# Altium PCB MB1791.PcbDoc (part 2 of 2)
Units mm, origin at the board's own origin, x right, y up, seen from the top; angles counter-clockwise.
Board outline 68.69 x 34.35 mm, 2 copper layers (Top Layer, Bottom Layer), stack 0.78 mm thick; 94 components, 70 nets, 269 pads, 1128 vias.
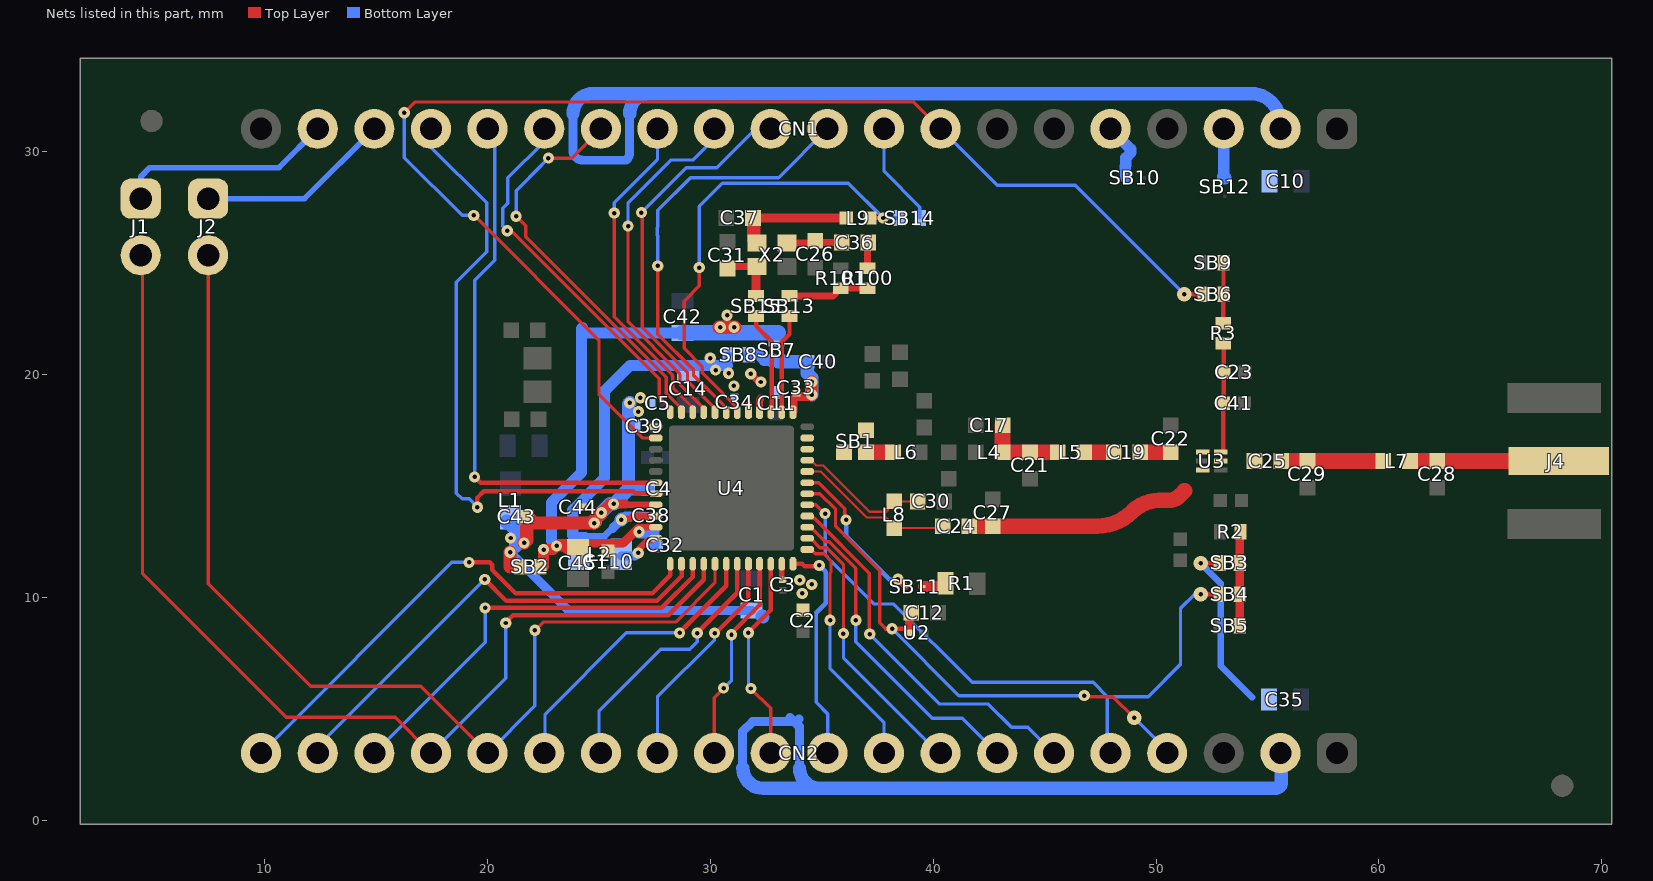
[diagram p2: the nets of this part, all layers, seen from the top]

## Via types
v1: diameter 0.5, hole 0.2, Top Layer to Bottom Layer, 1122 vias
v2: diameter 0.65, hole 0.2, Top Layer to Bottom Layer, 6 vias

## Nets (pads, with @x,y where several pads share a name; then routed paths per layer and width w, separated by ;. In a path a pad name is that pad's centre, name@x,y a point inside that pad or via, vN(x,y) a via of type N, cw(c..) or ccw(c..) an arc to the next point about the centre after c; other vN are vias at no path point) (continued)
NetC17_2: C17.2 C21.2 L4.2 L5.1 | length 3.7
  Top Layer w0.7: C17.2@43.117,17.72 43.112,17.715 L4.2@43.112,16.52 C21.2@44.349,16.52 L5.1@45.585,16.52
NetC19_1: C19.1 C22.2 U3.1 | length 1.4
  Top Layer w0.7: C19.1@49.295,16.52 C22.2@50.655,16.52
NetC19_2: C19.2 L5.2 | length 1.3
  Top Layer w0.7: L5.2@46.783,16.52 C19.2@48.061,16.52
NetC23_2: C23.2 C41.1 R3.1 U3.6 | length 4.9
  Top Layer w0.2: U3.6@52.9,16.52 53.019,16.639 C41.1@53.019,18.704 53.034,18.718 C23.2@53.034,20.104 53.034,21.384 R3.1@53.014,21.404
NetC24_2: C24.2 C27.2 U3.3 | length 10.3
  Top Layer w0.7: C24.2@41.666,13.197 C27.2@42.681,13.197 42.681,13.203 47.371,13.203 ccw(c47.371,15.407) 48.93,13.848 ; 49.09,14.009 48.931,13.849 ; 51.046,14.553 cw(c50.567,15.033) 50.567,14.355 50.153,14.355 ccw(c50.153,12.625) 48.931,13.849 ; 51.047,14.554 51.275,14.782 ; 48.93,13.848 cw(c50.153,12.625) 48.931,13.849 ; 48.93,13.848 48.931,13.849
NetC25_1: C25.1 U3.5
NetC25_2: C25.2 C29.1 L7.1 | length 4.6
  Top Layer w0.7: C25.2@55.613,16.12 C29.1@56.792,16.121 L7.1@60.196,16.12
NetC26_1: C26.1 C36.2 X2.1 | length 2.6
  Top Layer w0.2: X2.1@33.255,25.898 X2.1@33.445,25.898 ; C26.1@34.657,25.898 C26.1@34.679,25.92
  Top Layer w0.3: X2.1@33.445,25.898 C26.1@34.657,25.898 ; C26.1@34.679,25.92 C36.2@35.86,25.92
NetC28_1: C28.1 J4.1 L7.2 | length 6.7
  Top Layer w0.7: L7.2@61.394,16.12 62.568,16.12 J4.1@68.06,16.12
NetC31_1: C31.1 SB15.2 X2.3 | length 2.7
  Top Layer w0.254: C31.1@30.778,24.793 C31.1@30.833,24.848
  Top Layer w0.3: C31.1@30.833,24.848 X2.3@32.095,24.848
  Top Layer w0.4: SB15.2@32.06,23.52 32.06,24.813 X2.3@32.095,24.848
NetC36_1: C36.1 R100.2 | length 1.1
  Top Layer w0.3: R100.2@37.06,24.77 C36.1@37.06,25.918
NetC37_2: C37.2 L9.1 X2.2 | length 5.3
  Top Layer w0.4: C37.2@31.958,27.02 L9.1@36.06,27.02
  Top Layer w0.625: C37.2@31.958,27.02 31.958,26.035 X2.2@32.095,25.898
NetCN1_3: CN1.3 SB12.1 | length 2.2
  Bottom Layer w0.5: SB12.1@53.04,28.863 CN1.3@53.04,31.02
  Bottom Layer w0.6: SB12.1@53.04,28.863 SB12.1@53.077,28.826
NetCN1_5: CN1.5 SB10.1 | length 2.7
  Bottom Layer w0.5: CN1.5@47.96,31.02 48.877,30.103 48.877,29.954 48.643,29.72 48.643,29.37 48.618,29.345 48.618,29.055 48.643,29.03 SB10.1@48.643,28.825
NetL2_2: L2.2 U4.47 | length 2
  Top Layer w0.3: v1(26.78,12) 26.818,12.038 26.818,12.168 27.222,12.572 27.328,12.572 27.408,12.652 U4.47@27.558,12.652
  Bottom Layer w0.4: L2.2@26.032,11.86 26.622,11.86 v1@26.8,12.037
NetL6_1: L6.1 SB1.2 | length 1.2
  Top Layer w0.7: SB1.2@36.991,16.52 L6.1@38.203,16.52
NetR1_2: R1.2 SB11.1 | length 1
  Top Layer w0.5: SB11.1@39.585,10.489 40.429,10.489 R1.2@40.56,10.62
NetR2_2: R2.2 SB3.2 SB4.2 SB5.2 | length 4.2
  Top Layer w0.4: SB5.2@53.754,8.734 SB4.2@53.754,10.148 SB3.2@53.754,11.548 53.754,12.916 R2.2@53.786,12.948
NetR3_2: R3.2 SB6.2 SB9.2 | length 2.7
  Top Layer w0.2: R3.2@53.014,22.304 53.014,23.592 SB6.2@53.027,23.604 SB9.2@53.027,25.005
NetR100_1: R100.1 R101.1 SB13.2 | length 3.8
  Top Layer w0.2: SB13.2@33.56,23.52 SB13.2@33.66,23.62
  Top Layer w0.3: SB13.2@33.56,23.52 35.51,23.52 R101.1@35.86,23.87 R100.1@37.06,23.87
NetSB1_1: SB1.1 U4.23
NetSB1_3: SB1.3 U4.22
NetSB11_2: SB11.2 U4.19 | length 7
  Top Layer w0.15: U4.19@34.356,15.152 34.871,15.152 36.04,13.983 v1@36.04,13.5
  Top Layer w0.2: v1(38.42,10.82) v1@38.429,10.82
  Top Layer w0.3: v1@38.429,10.82 SB11.2@38.76,10.489
  Bottom Layer w0.2: v1(36.1,13.48) 36.1,12.84 36.06,12.8 38.06,10.8 38.42,10.8 v1(38.42,10.82)
NetSB13_1: SB13.1 U4.26 | length 4.5
  Top Layer w0.2: U4.26@33.218,18.302 33.218,21.458 33.56,21.8 SB13.1@33.56,22.62
NetSB15_1: SB15.1 U4.27 | length 4.6
  Top Layer w0.2: SB15.1@32.06,22.62 32.06,22.18 32.77,21.47 32.77,18.354 U4.27@32.718,18.302
NRST: C12.1 CN2.4 U2.1 U4.18 | length 24.6
  Top Layer w0.15: U4.18@34.356,14.652 34.925,14.652 35.625,13.952 35.625,13.195 37.615,11.205 37.615,8.865 37.88,8.6 ; v1(46.779,5.598) 46.757,5.576 46.757,5.554 48.065,5.554 v2(49.02,4.598)
  Top Layer w0.2: 37.88,8.6 v1(38.16,8.6) 38.868,8.6 U2.1@38.948,8.52 ; C12.1@38.948,9.208 C12.1@39.06,9.32
  Top Layer w0.4: U2.1@38.948,8.52 C12.1@38.948,9.208
  Bottom Layer w0.15: v1(38.16,8.6) 41.162,5.598 v1(46.779,5.598) ; v2(49.02,4.598) 50.5,3.119 CN2.4@50.5,3.02
PA0: CN2.14 U4.7 | length 11.8
  Top Layer w0.2: v1(29.42,8.4) 29.42,8.42 31.218,10.218 U4.7@31.218,11.505
  Bottom Layer w0.15: CN2.14@25.1,3.02 25.015,3.105 25.015,4.905 27.793,7.683 29.087,7.683 29.42,8.017 v1(29.42,8.4)
PA1: CN2.13 U4.8 | length 10.2
  Top Layer w0.2: v1(30.2,8.4) 30.24,8.4 31.718,9.878 U4.8@31.718,11.505
  Bottom Layer w0.15: CN2.13@27.64,3.02 27.64,5.542 30.2,8.102 v1(30.2,8.4)
PA2: CN2.12 U4.9 | length 9.3
  Top Layer w0.15: CN2.12@30.18,3.02 30.18,5.51 v1(30.608,5.938)
  Top Layer w0.2: v1@30.96,8.4 32.218,9.658 U4.9@32.218,11.505
  Bottom Layer w0.15: v1(30.608,5.938) 30.96,6.29 v1(30.96,8.33)
PA3: CN2.11 U4.10 | length 9.4
  Top Layer w0.15: v1(31.832,5.917) 32.72,5.028 CN2.11@32.72,3.02
  Top Layer w0.2: v1@31.66,8.38 32.718,9.438 U4.10@32.718,11.505
  Bottom Layer w0.15: v1(31.72,8.42) 31.72,6.028 v1(31.832,5.917)
PA4: CN2.10 U4.12 | length 10.2
  Top Layer w0.2: U4.12@33.718,11.505 34.135,11.505 34.247,11.393 34.852,11.393 v1(34.897,11.438)
  Bottom Layer w0.15: 34.76,9.311 34.76,5.291 35.278,4.773 35.278,3.038 CN2.10@35.26,3.02
  Bottom Layer w0.2: 34.76,9.311 35.186,9.737 35.186,11.149 v1(34.897,11.438) v1@34.86,11.401
PA5: CN2.9 U4.13 | length 10.9
  Top Layer w0.15: U4.13@34.356,12.152 34.537,12.152 34.726,11.963 35.114,11.963 35.422,11.655 35.422,11.13 35.38,11.088 v1(35.38,8.98)
  Bottom Layer w0.15: v1(35.38,8.98) 35.38,6.803 37.8,4.383 CN2.9@37.8,3.02
PA6: CN2.8 U4.14 | length 12.4
  Top Layer w0.15: U4.14@34.356,12.652 34.507,12.652 34.926,12.233 35.226,12.233 35.98,11.479 v1(35.98,8.38)
  Bottom Layer w0.15: v1(35.98,8.38) 35.98,7.305 40.265,3.02 CN2.8@40.34,3.02
PA7: CN2.7 U4.15 | length 14.7
  Top Layer w0.15: U4.15@34.356,13.152 34.507,13.152 35.156,12.503 35.338,12.503 36.54,11.301 v1(36.54,8.98)
  Bottom Layer w0.15: v1(36.54,8.98) 36.54,8.004 39.958,4.585 41.315,4.585 CN2.7@42.88,3.02
PA8: CN2.6 U4.16 | length 17.1
  Top Layer w0.15: U4.16@34.356,13.652 34.574,13.652 34.645,13.58 34.645,13.542 34.684,13.542 37.14,11.085 v1@37.14,8.46
  Top Layer w0.2: v1@37.14,8.46 37.14,8.38 v1(37.16,8.36) 37.16,8.4 v1@37.18,8.42
  Bottom Layer w0.15: v1(37.16,8.36) 40.3,5.219 42.484,5.219 43.518,4.185 44.255,4.185 CN2.6@45.42,3.02
PA9: CN2.5 SB4.1 U4.17 | length 29.1
  Top Layer w0.15: U4.17@34.356,14.152 34.748,14.152 35.14,13.76 v1@35.14,13.7
  Top Layer w0.2: v2(51.997,10.139) 52.846,10.139 SB4.1@52.854,10.148
  Bottom Layer w0.15: v1(35.16,13.76) 35.16,11.917 35.422,11.655 35.422,11.645 37.361,9.705 38.247,9.705 41.762,6.19 47.185,6.19 47.82,5.554 ; CN2.5@47.96,3.02 47.82,3.16 47.82,5.554 ; v2(51.997,10.139) 51.73,10.139 51.098,9.507 51.098,7.006 49.647,5.554 47.82,5.554
PA10: CN1.12 U4.33 | length 16.3
  Top Layer w0.15: v1(26.32,26.66) 26.32,22.356 28.577,20.099 28.577,20.096 28.648,20.025 28.648,19.562 29.718,18.492 U4.33@29.718,18.302
  Bottom Layer w0.15: v1(26.32,26.66) 26.32,27.699 28.241,29.621 29.227,29.621 30.18,30.573 CN1.12@30.18,31.02
PA11: CN1.13 U4.34 | length 15
  Top Layer w0.15: v1(25.7,27.24) 25.7,22.594 28.307,19.987 28.307,19.935 28.326,19.916 28.326,19.404 U4.34@29.218,18.512
  Top Layer w0.2: U4.34@29.218,18.302 U4.34@29.218,18.512
  Bottom Layer w0.15: v1(25.7,27.24) 25.7,27.701 27.64,29.641 CN1.13@27.64,31.02
PA12: CN1.14 U4.35 | length 18.1
  Top Layer w0.15: v1@21.27,27.15 v1@21.35,27.15 ; v1(21.3,27.1) 21.73,26.67 21.73,26.182 28.037,19.875 28.037,19.152 28.718,18.471 U4.35@28.718,18.302 ; v1(22.75,29.703) 23.783,29.703 CN1.14@25.1,31.02
  Bottom Layer w0.15: v1(21.3,27.1) 21.3,28.249 22.47,29.42 22.47,29.424 v1(22.75,29.703)
PA13: CN1.15 U4.36 | length 16.7
  Top Layer w0.15: v1(20.899,26.446) 20.981,26.365 21.164,26.365 27.725,19.803 27.725,18.976 28.218,18.482 U4.36@28.218,18.302
  Bottom Layer w0.15: v1(20.899,26.446) 20.705,26.641 20.705,27.452 20.931,27.679 20.931,28.82 22.56,30.449 CN1.15@22.56,31.02
PA14: CN1.16 U4.42 | length 24.5
  Top Layer w0.2: v1(19.437,15.408) 19.705,15.14 27.618,15.14 U4.42@27.66,15.182
  Bottom Layer w0.15: v1(19.437,15.408) 19.437,24.224 20.341,25.128 20.341,30.699 CN1.16@20.02,31.02 CN1.16@20.008,31.008
PA15: CN1.17 U4.43 | length 27.8
  Top Layer w0.2: v1(19.564,14.048) 19.564,14.482 19.852,14.77 26.543,14.77 26.646,14.666 27.629,14.666 U4.43@27.653,14.69
  Bottom Layer w0.15: CN1.17@17.48,31.02 17.48,30.202 19.981,27.7 19.981,25.508 18.62,24.147 18.62,14.678 18.877,14.421 19.191,14.421 v1(19.564,14.048)
PB0: L9.2 SB14.1 U4.30 | length 21.2
  Top Layer w0.15: v1(29.514,24.793) 29.514,23.975 28.833,23.294 28.833,21.177 29.651,20.359 29.651,20.076 U4.30@31.218,18.508 ; U4.30@31.155,18.365 U4.30@31.218,18.302 U4.30@31.218,18.508 ; U4.30@31.218,18.514 U4.30@31.218,18.508
  Top Layer w0.2: L9.2@37.22,27.02 v1(37.76,27.02)
  Bottom Layer w0.15: v1(29.514,24.793) 29.514,27.539 30.554,28.578 36.202,28.578 v1(37.76,27.02)
  Bottom Layer w0.2: v1(37.76,27.02) SB14.1@38.51,27.02
PB2: CN1.10 U4.31 | length 19.5
  Top Layer w0.15: v1(27.654,24.873) 27.654,21.812 29.255,20.212 29.255,19.967 30.718,18.504 U4.31@30.718,18.302
  Bottom Layer w0.15: v1(27.654,24.873) 27.654,26.225 27.635,26.244 27.635,26.596 27.654,26.615 27.654,27.362 29.121,28.828 33.068,28.828 CN1.10@35.26,31.02
PB3: CN2.20 U4.1 | length 23.4
  Top Layer w0.2: v1@19.197,11.581 20.111,11.581 20.234,11.458 20.234,11.234 21.288,10.18 27.4,10.18 28.211,10.991 U4.1@28.211,11.505
  Bottom Layer w0.15: CN2.20@9.86,3.02 18.415,11.575 v1(19.191,11.575)
PB4: CN2.19 U4.2 | length 20.8
  Top Layer w0.2: v1(19.892,10.814) 20.848,9.857 27.617,9.857 28.718,10.958 U4.2@28.718,11.505
  Bottom Layer w0.15: CN2.19@12.4,3.322 v1(19.892,10.814)
PB5: CN2.18 U4.3 | length 19
  Top Layer w0.2: v1(19.908,9.535) 20.558,9.533 27.833,9.533 29.218,10.918 U4.3@29.218,11.505
  Bottom Layer w0.15: CN2.18@14.94,3.02 19.908,7.988 v1(19.908,9.535)
PB6: CN2.17 J1.2 U4.4 | length 48.2
  Top Layer w0.15: J1.2@4.46,25.35 4.538,25.272 4.538,11.077 10.992,4.623 15.877,4.623 CN2.17@17.48,3.02
  Top Layer w0.2: v1(20.836,8.855) 20.84,8.889 21.16,9.209 28.129,9.209 29.718,10.798 U4.4@29.718,11.505
  Bottom Layer w0.15: CN2.17@17.48,3.02 20.836,6.376 v1(20.836,8.855)
PB7: CN2.16 J2.2 U4.5 | length 46.6
  Top Layer w0.15: J2.2@7.485,25.348 7.485,10.61 12.08,6.015 17.025,6.015 CN2.16@20.02,3.02 ; v1@22.141,8.532 22.506,8.896 28.456,8.896 30.218,10.658 U4.5@30.218,11.505
  Bottom Layer w0.15: CN2.16@20.02,3.02 22.139,5.139 v1(22.139,8.53)
PB8: CN2.15 U4.6 | length 14.2
  Top Layer w0.15: U4.6@30.678,11.465 U4.6@30.718,11.505 U4.6@30.718,11.255
  Top Layer w0.2: v1@28.62,8.36 v1@28.66,8.4 ; v1@28.7,8.4 v1@28.66,8.4 ; U4.6@30.72,11.255 U4.6@30.72,11.58 ; U4.6@30.72,11.465 U4.6@30.72,11.58 ; v1@28.66,8.4 28.64,8.4 v1(28.63,8.41) 28.62,8.42 30.72,10.52 U4.6@30.72,11.58
  Bottom Layer w0.15: CN2.15@22.56,3.02 22.596,3.056 22.596,4.761 26.244,8.41 v1(28.63,8.41)
PB12: CN1.11 U4.32 | length 17.8
  Top Layer w0.15: v1@26.96,27.2 26.96,22.125 28.985,20.1 28.985,19.716 30.218,18.483 U4.32@30.218,18.302
  Bottom Layer w0.15: v1(26.92,27.26) 28.933,29.273 30.298,29.273 32.045,31.02 CN1.11@32.72,31.02 CN1.11@32.72,30.844
PC13: CN1.8 SB6.1 U4.38 | length 59.7
  Top Layer w0.15: v1(16.28,31.74) 16.76,32.22 39.14,32.22 CN1.8@40.34,31.02 ; v1@19.266,27.14 v1(19.4,27.14) ; v1@19.35,27.21 25.015,21.545 25.015,19.108 26.971,17.152 U4.38@27.558,17.152
  Top Layer w0.2: v2(51.274,23.6) SB6.1@52.122,23.6
  Bottom Layer w0.15: v1(16.28,31.74) 16.287,31.733 16.287,29.728 18.875,27.14 v1(19.4,27.14) ; CN1.8@40.34,31.02 42.869,28.491 46.383,28.491 v2(51.274,23.6)
RFI_N: C30.2 L8.2 U4.21 | length 6.1
  Top Layer w0.1: U4.21@34.578,16.095 34.759,15.914 35.077,15.914 37.147,13.845 37.905,13.845 37.964,13.904 37.964,14.012 L8.2@38.264,14.312 ; L8.2@38.398,14.446 L8.2@38.264,14.312 ; C30.2@39.276,14.307 38.269,14.307 L8.2@38.264,14.312
RFI_P: C24.1 L8.1 U4.20 | length 7.3
  Top Layer w0.1: U4.20@34.356,15.652 34.357,15.651 34.968,15.651 37.037,13.581 37.905,13.581 37.964,13.523 37.964,13.414 L8.1@38.264,13.114 40.385,13.114 C24.1@40.468,13.197
UART_RX: CN1.18 J2.1 | length 8.8
  Bottom Layer w0.254: J2.1@7.485,27.888 11.808,27.888 CN1.18@14.94,31.02
UART_TX: CN1.19 J1.1 | length 9.8
  Bottom Layer w0.254: J1.1@4.46,27.89 4.46,28.873 4.869,29.281 10.661,29.281 CN1.19@12.4,31.02
VDD: C1.2 C2.2 C3.2 C4.2 C5.2 C35.2 C39.1 C43.2 C44.2 CN2.2 L1.1 SB2.2 SB3.1 U4.11 U4.37 U4.44 | length 71
  Top Layer w0.2: v2(51.997,11.539) 52.846,11.539 SB3.1@52.854,11.548
  Top Layer w0.254: C3.2@33.22,10.9 U4.11@33.22,11.463
  Top Layer w0.3: v1@25.63,14.108 v1@25.674,14.152 ; 26.074,14.212 26.205,14.212 26.265,14.152 U4.44@27.558,14.152
  Top Layer w0.4: v1(25.67,14.195) 26.188,14.195
  Top Layer w0.5: v1(25.127,13.8) 25.522,14.195 v1(25.67,14.195)
  Top Layer w0.6: v1(21.026,12.027) 21.026,11.381 SB2.2@21.376,11.381 ; v1(21.657,12.45) 21.771,12.563 21.771,13.201 ; C43.2@21.803,13.631 22.095,13.338 v1(24.805,13.338) 24.805,13.478 v1(25.127,13.8)
  Bottom Layer w0.3: v2(51.997,11.539) 52.904,10.633 52.904,6.927 54.307,5.524
  Bottom Layer w0.4: v1(21.026,12.027) 23.634,9.418 C1.2@31.859,9.418 ; 31.461,2.547 31.461,3.861 31.461,3.993 31.904,4.435 33.77,4.435 ; 33.579,4.626 33.77,4.435 ; 33.99,4.54 33.885,4.435 33.77,4.435 ; 34.001,2.547 34.001,3.861 34.001,4.204 33.77,4.435
  Bottom Layer w0.45: C4.2@27.212,14.863 C4.2@27.224,14.876
  Bottom Layer w0.6: L1.1@20.871,13.357 20.871,13.433 21.28,13.023 21.28,12.299 ; v1(24.805,13.338) 24.805,13.347 24.849,13.391 24.849,13.522 v1(25.127,13.8) 25.127,13.819 v1@25.523,14.215 ; v1(25.67,14.195) 26.338,14.863 ; v1(26.39,18.729) 26.338,18.677 26.338,14.863 ; C4.2@27.212,14.863 26.338,14.863 ; 31.471,2.346 ccw(c32.377,2.346) 32.377,1.441 55.348,1.441 ccw(c55.348,1.718) 55.625,1.718 55.625,2.975 ccw(c55.58,2.975) CN2.2@55.58,3.02 ; C1.2@32.345,9.15 32.37,9.125 ; 34.011,2.346 ccw(c34.917,2.346) 34.917,1.441
  other v1: 34.134,10.184 34.558,10.583 34.023,10.779 21.052,12.667 26.784,18.335 26.876,18.957
VDD_TCXO_EXT: CN1.9 SB14.2 | length 4.7
  Bottom Layer w0.15: CN1.9@37.8,31.02 37.8,29.115 39.41,27.505 SB14.2@39.41,27.02
VDDPA: C33.2 C40.1 SB7.1 SB8.2 U4.25 | length 6.5
  Top Layer w0.35: U4.25@33.743,18.327 33.743,18.905 C33.2@33.876,19.039
  Top Layer w0.4: C33.2@33.876,19.039 33.903,19.012 v1@34.539,19.012
  Top Layer w0.5: v1@34.558,19.063 v1@34.558,19.713
  Bottom Layer w0.5: SB8.2@31.729,20.818 SB8.2@31.729,20.893 32.163,20.893 32.413,20.643 SB7.1@32.98,20.643 SB7.1@33.047,20.576
  Bottom Layer w0.6: SB7.1@33.047,20.576 C40.1@34.372,20.576 34.362,20.565 34.362,20.05 34.558,19.854 v1(34.558,19.669) v1(34.558,19.093)
VDDRF: C10.1 C11.1 C32.2 C42.1 C45.1 C110.1 CN1.2 SB2.1 SB7.2 U4.28 U4.46 | length 77.9
  Top Layer w0.3: v1@26.696,13.002 v1@26.75,13.002 ; v1@26.758,13.152 U4.46@27.558,13.152 U4.46@27.569,13.152 ; v1(31.825,20.034) 32.194,19.665 v1(32.28,19.665) ; U4.28@32.218,18.302 32.218,18.861 32.262,18.905 32.262,18.959
  Top Layer w0.4: v1(23.114,12.316) 23.23,12.432 26.1,12.432 ; 23.481,12.432 26.1,12.432 ; C45.1@23.594,12.432 26.1,12.432 ; C45.1@24.071,12.432 26.1,12.432 ; v1@26.696,13.002 v1@26.669,13.002 ; v1@26.736,13.069 v1@26.669,13.002 ; 26.1,12.432 v1@26.669,13.002
  Top Layer w0.5: SB2.1@22.386,11.381 22.534,11.381 v1(22.534,12.144) 22.942,12.144 v1(23.114,12.316) 23.481,12.316 C45.1@23.594,12.203
  Top Layer w0.6: v1@30.409,22.128 v1@31.109,22.128
  Bottom Layer w0.4: 23.841,31.493 23.841,30.179 23.841,30.039 ccw(c24.247,30.039) 23.96,29.752 ccw(c24.306,30.098) 24.306,29.609 26.164,29.609 ccw(c26.164,29.758) 26.269,29.653 ccw(c26,29.922) 26.381,29.922 26.381,30.179 26.381,31.493
  Bottom Layer w0.5: v1(22.534,12.144) 22.942,12.144 v1(23.114,12.316) 22.889,12.541 22.889,14.261 24.23,15.603 24.23,22.061 ; 24.283,22.114 24.23,22.061 ; 27.475,12.372 27.475,12.922 ; C42.1@28.764,21.868 24.423,21.868 24.23,22.061
  Bottom Layer w0.6: 23.851,31.694 cw(c24.757,31.694) 24.757,32.599 27.297,32.599 ; 26.391,31.694 cw(c27.297,31.694) 27.297,32.599 ; v1@26.809,12.941 v1@26.828,12.96 ; v1(26.818,12.95) 27.344,12.95 ; CN1.2@55.58,31.02 55.58,31.242 ccw(c54.192,31.242) 55.173,32.224 ccw(c54.267,31.318) 54.267,32.599 27.297,32.599
  Bottom Layer w0.7: C42.1@28.753,21.879 33.043,21.879
  other v1: 30.452,22.122 31.077,22.122 30.764,22.659
VDDRF1V55: C14.1 C34.2 C38.1 L2.1 SB8.1 U4.29 U4.45 | length 20.4
  Top Layer w0.3: v1(26.019,13.486) 26.058,13.524 26.42,13.524 26.547,13.652 U4.45@27.558,13.652 ; U4.29@31.718,18.302 31.718,18.655
  Bottom Layer w0.3: L2.1@24.107,11.94 23.808,12.239 23.808,12.776 23.841,12.776 24.413,12.776 24.45,12.738 25.262,12.738 25.262,12.752 25.668,13.158 ; v1@25.969,13.486 v1(26.019,13.486) ; v1@26.039,13.505 v1(26.019,13.486) ; v1@26.074,13.486 v1(26.019,13.486) ; 30.788,20.407 30.788,20.867 SB8.1@30.83,20.909
  Bottom Layer w0.4: 25.668,13.158 25.668,13.138 25.632,13.101 25.635,13.101 v1(26.019,13.486) ; v1@26.039,13.505 26.198,13.665 C38.1@26.998,13.665
  Bottom Layer w0.5: 23.841,12.776 23.841,13.927 25.266,15.352 25.266,19.258 26.415,20.407 30.788,20.407
  Bottom Layer w0.6: v1(26.019,13.486) v1@26.039,13.505
  other v1: 31.066,19.492 30.832,20.057 30.247,20.201 30.008,20.737
pads on no net: 1.1 1_1.1 ?.1 _1.1 Designator1.1
copper on no net: | length 1771.3
  Top Layer w0.025: 88.999,130.962 91.531,133.494 94.579,136.542 97.627,139.59 100.675,142.638 103.723,145.686 106.771,148.734 109.819,151.782 ; 88.999,132.486 90.007,133.494 93.055,136.542 96.103,139.59 99.151,142.638 102.199,145.686 105.247,148.734 108.295,151.782 ; 88.999,134.01 91.531,136.542 94.579,139.59 97.627,142.638 100.675,145.686 103.723,148.734 106.771,151.782 ; 88.999,135.534 90.007,136.542 93.055,139.59 96.103,142.638 99.151,145.686 102.199,148.734 105.247,151.782 ; 88.999,137.058 91.531,139.59 94.579,142.638 97.627,145.686 100.675,148.734 103.723,151.782 ; 88.999,138.582 90.007,139.59 93.055,142.638 96.103,145.686 99.151,148.734 102.199,151.782 ; 88.999,140.106 91.531,142.638 94.579,145.686 97.627,148.734 100.675,151.782 ; 88.999,141.63 90.007,142.638 93.055,145.686 96.103,148.734 99.151,151.782 ; 88.999,143.154 91.531,145.686 94.579,148.734 97.627,151.782 ; 88.999,144.678 90.007,145.686 93.055,148.734 96.103,151.782 ; 88.999,146.202 91.531,148.734 94.579,151.782 ; 88.999,147.726 90.007,148.734 93.055,151.782 ; 88.999,149.25 91.531,151.782 ; 88.999,150.774 90.007,151.782 ; 90.007,130.446 93.055,133.494 96.103,136.542 99.151,139.59 102.199,142.638 105.247,145.686 108.295,148.734 111.343,151.782 ; 91.531,130.446 94.579,133.494 97.627,136.542 100.675,139.59 103.723,142.638 106.771,145.686 109.819,148.734 112.867,151.782 ; 93.055,130.446 96.103,133.494 99.151,136.542 102.199,139.59 105.247,142.638 108.295,145.686 111.343,148.734 114.391,151.782 ; 94.579,130.446 97.627,133.494 100.675,136.542 103.723,139.59 106.771,142.638 109.819,145.686 112.867,148.734 115.915,151.782 ; 96.103,130.446 99.151,133.494 102.199,136.542 105.247,139.59 108.295,142.638 111.343,145.686 114.391,148.734 117.439,151.782 ; 97.627,130.446 100.675,133.494 103.723,136.542 106.771,139.59 109.819,142.638 112.867,145.686 115.915,148.734 117.439,150.258 ; 99.151,130.446 102.199,133.494 105.247,136.542 108.295,139.59 111.343,142.638 114.391,145.686 117.439,148.734 ; 100.675,130.446 103.723,133.494 106.771,136.542 109.819,139.59 112.867,142.638 115.915,145.686 117.439,147.21 ; 102.199,130.446 105.247,133.494 108.295,136.542 111.343,139.59 114.391,142.638 117.439,145.686 ; 103.723,130.446 106.771,133.494 109.819,136.542 112.867,139.59 115.915,142.638 117.439,144.162 ; 105.247,130.446 108.295,133.494 111.343,136.542 114.391,139.59 117.439,142.638 ; 106.771,130.446 109.819,133.494 112.867,136.542 115.915,139.59 117.439,141.114 ; 108.295,130.446 111.343,133.494 114.391,136.542 117.439,139.59 ; 109.819,130.446 112.867,133.494 115.915,136.542 117.439,138.066 ; 111.343,130.446 114.391,133.494 117.439,136.542 ; 112.867,130.446 115.915,133.494 117.439,135.018 ; 114.391,130.446 117.439,133.494 ; 115.915,130.446 117.439,131.97
  Top Layer w0.381: 2.154,133.494 12.565,133.494 36.181,133.494 58.019,133.494 74.525,133.494 88.999,133.494 117.439,133.494 ; 2.154,136.542 12.565,136.542 36.181,136.542 58.019,136.542 74.525,136.542 88.999,136.542 117.439,136.542 ; 2.154,139.59 12.565,139.59 36.181,139.59 58.019,139.59 74.525,139.59 88.999,139.59 117.439,139.59 ; 2.154,142.638 12.565,142.638 36.181,142.638 58.019,142.638 74.525,142.638 88.999,142.638 117.439,142.638 ; 2.154,145.686 12.565,145.686 36.181,145.686 58.019,145.686 74.525,145.686 88.999,145.686 117.439,145.686 ; 2.154,148.734 12.565,148.734 36.181,148.734 58.019,148.734 74.525,148.734 88.999,148.734 117.439,148.734 ; 2.154,151.782 117.439,151.782 ; 12.565,154.83 12.565,130.446 ; 36.181,154.83 36.181,130.446 ; 58.019,154.83 58.019,130.446 ; 74.525,154.83 74.525,130.446 ; 88.999,154.83 88.999,130.446 ; 12.565,130.446 36.181,130.446 ; 12.565,130.446 2.154,130.446 2.154,154.83 117.439,154.83 117.439,130.446 88.999,130.446 ; 36.181,130.446 58.019,130.446 ; 58.019,130.446 74.525,130.446 ; 74.525,130.446 88.999,130.446

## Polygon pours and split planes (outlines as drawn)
GND on Top Layer "TOP_LAYER_GND" (solid, remove dead copper, pour order 0): 1.751,34.02 70.439,34.02 70.439,0.02 1.751,0.02
GND on Bottom Layer "GND_L04_P002" (solid, remove dead copper, pour order 2): 1.751,34.04 70.439,34.04 70.439,0 1.751,0

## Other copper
Top Layer:
  region net VDD: 33.085,10.655 33.085,10.943 33.49,10.943 33.651,11.002 cw(c34.123,9.716) 34.123,11.086 34.283,11.086 cw(c34.283,10.726) 34.421,11.058 cw(c34.014,10.077) 34.765,10.828 34.817,10.777 cw(c34.585,10.546) 34.912,10.546 34.912,9.867 cw(c34.21,9.867) 34.706,9.37 34.464,9.127 33.863,9.127 33.86,10.284 ccw(c33.557,10.284) 33.675,10.562 33.457,10.655
  region net VDD: 27.52,17.503 27.368,17.503 cw(c27.368,18.022) 27.001,17.655 26.156,18.499 cw(c26.393,18.737) 26.156,18.974 26.481,19.299 cw(c26.839,18.942) 27.196,19.299 cw(c26.912,19.015) 27.314,19.015 27.314,18.331 ccw(c28.018,18.331) 27.486,17.87 cw(c27.38,17.777) 27.52,17.777
  region net NetC15_1: 34.16,17.652 34.16,18.02 36.079,19.838 cw(c36.751,19.128) 36.751,20.105 36.913,20.105 38.91,20.105 38.91,19.347 36.928,19.347 ccw(c36.928,17.777) 35.857,18.925 34.492,17.652
  region net NetC24_2: 51.821,15.775 cw(c51.115,16.07) 51.529,15.426 51.127,15.168 50.976,14.953 51.494,14.59 ccw(c51.533,14.646) 51.589,14.607 51.71,14.781 51.819,15.287 cw(c52.277,15.188) 51.893,15.457 52.019,15.637
  region net VDDRF: 31.666,19.832 31.616,19.881 cw(c31.772,20.037) 31.552,20.037 31.552,20.107 ccw(c31.115,20.108) 31.424,20.417 30.302,21.538 cw(c30.774,22.011) 30.106,22.011 30.106,22.416 cw(c30.658,22.416) 30.658,22.968 30.92,22.968 cw(c30.92,22.414) 31.473,22.414 31.473,21.83 ccw(c32.325,21.83) 31.723,21.228 32.135,20.816 cw(c31.784,20.465) 32.28,20.465 32.28,19.665
  region net VDDRF: 32.063,18.6 32.063,19.035 ccw(c31.094,19.035) 31.779,19.72 31.612,19.888 cw(c31.732,20.008) 31.562,20.008 31.562,20.089 cw(c31.701,20.089) 31.603,20.186 31.678,20.262 cw(c31.759,20.18) 31.759,20.295 31.894,20.295 cw(c31.894,19.981) 32.116,20.203 32.449,19.87 cw(c32.221,19.641) 32.544,19.646 cw(c32.321,19.671) 32.521,19.57 32.521,18.88 cw(c32.403,18.88) 32.486,18.796 32.377,18.6
  region net VDDRF1V55: 29.777,20.907 ccw(c30.004,20.759) 29.813,20.567 29.896,20.484 29.969,20.194 ccw(c30.305,20.279) 30.067,20.028 31.628,18.548 31.865,18.548 31.865,18.677 ccw(c31.296,18.677) 31.698,19.08 31.562,19.215 cw(c31.792,19.445) 31.467,19.445 31.467,19.477 31.467,19.561 ccw(c30.367,19.562) 31.145,20.34 30.611,20.873 ccw(c30.166,20.429) 30.166,21.058 30.056,21.058 ccw(c30.056,20.725)
  region net VDD: 21.501,11.716 20.936,11.716 cw(c20.936,11.97) 20.682,11.97 20.682,12.787 cw(c21.001,12.787) 21.001,13.106 21.696,13.106 cw(c21.696,12.795) 22.006,12.795 22.006,12.398 cw(c21.58,12.398) 21.881,12.096
  region net VDDRF: 22.349,12.308 22.621,12.58 cw(c22.747,12.454) 22.747,12.632 25.99,12.632 26.704,12.715 25.803,11.907 22.477,11.88 cw(c22.477,11.939) 22.428,11.907 22.349,12.024
  region net VDD: 25.47,13.849 25.575,13.849 ccw(c25.575,14.415) 25.975,14.014 25.67,14.195
  region net VDDRF: 26.931,12.736 ccw(c26.926,12.147) 26.513,12.567 26.374,12.706 26.669,13.002
  region net NetC25_1: 52.791,16.232 53.232,16.232 ccw(c53.232,16.998) 53.522,16.289 53.964,16.47 54.227,16.47 54.227,15.77 53.946,15.77 53.47,15.971 ccw(c53.288,15.54) 53.288,16.008 52.791,16.008
  region net NetC19_1: 52.184,16.632 51.744,16.632 cw(c51.744,17.398) 51.454,16.689 51.012,16.87 50.749,16.87 50.749,16.17 51.03,16.17 51.506,16.371 cw(c51.688,15.94) 51.688,16.408 52.184,16.408
  region net NetSB1_1: 34.356,17.301 34.642,17.301 ccw(c34.642,18.013) 35.16,17.525 35.356,17.733 cw(c35.634,17.471) 35.634,17.853 36.991,17.853 36.991,17.153 35.606,17.153 ccw(c35.606,16.827) 35.433,17.103 cw(c35.081,17.664) 35.081,17.002 34.356,17.002
  region net NetSB1_3: 34.425,16.502 34.774,16.502 cw(c34.774,15.705) 35.353,16.252 ccw(c35.544,16.432) 35.544,16.17 35.86,16.17 35.86,16.871 35.546,16.871 35.104,16.801 34.425,16.801
  pour cut-out: 32.12,18.52 32.12,20.72 29.8,23.04 29.8,25.82 30.96,25.82 30.96,27.52 37.86,27.52 37.86,25.82 37.86,23.02 37.36,22.42 35.22,22.42 33.68,20.88 33.68,18.84 33.36,18.52
  pour cut-out: 37.477,11.969 40.809,11.969 40.809,13.968 40.12,13.968 40.12,15.434 36.729,15.434 36.3,15.934 36.3,15.434 36.3,11.963 37.671,11.963
  region net VDD: 24.219,14.226 24.37,14.376 25.551,14.376 25.822,14.105 24.854,13.136 24.219,13.136
  region net NetC28_1: 65.297,16.432 66.247,16.755 66.278,16.755 66.278,15.485 66.217,15.485 65.297,15.807
  pour cut-out: 27.78,18.06 34.1,18.06 34.04,18 34.04,11.78 28.38,11.78 28.38,12.36 27.78,12.36
  pour cut-out: 39.522,9.783 39.585,9.72 39.96,9.72 39.96,8.92 39.46,8.92
  pour cut-out: 31.16,27.42 31.66,27.42 31.66,26.52 31.56,26.62 31.16,26.62
  pour cut-out: 36.46,27.42 36.86,27.42 36.86,26.62 36.46,26.62
  pour cut-out: 36.26,26.32 36.76,26.32 36.76,25.62 36.66,25.52 36.26,25.52
  pour cut-out: 21.6,20.2 22.9,20.2 22.9,19.7 21.6,19.7
  region net GND: 33.76,25.22 35.46,25.22 35.66,25.02 35.66,24.42 35.16,24.42 34.06,24.42 33.96,24.52 33.76,24.52
  pour cut-out: 25.64,13.08 26.2,13.08 26.22,13.06 26.22,12.74 25.64,12.74 25.62,12.76 25.62,13.06
  pour cut-out: 34.16,19.54 34.72,19.54 34.74,19.52 34.74,19.2 34.16,19.2 34.14,19.22 34.14,19.52
  pour cut-out: 32.98,10.66 33.54,10.66 33.56,10.64 33.56,10.32 32.98,10.32 32.96,10.34 32.96,10.64
  text "Layer" at 3.932,152.544 h1.52
  text "Name" at 14.343,152.544 h1.52
  text "Material" at 37.959,152.544 h1.52
  text "Thickness" at 59.797,152.544 h1.52
  text "Constant" at 76.303,152.544 h1.52
  text "Board Layer Stack" at 90.777,152.544 h1.52
  text "Top Overlay" at 14.343,149.496 h1.52
  text "Top Solder" at 14.343,146.448 h1.52
  text "Solder Resist" at 37.959,146.448 h1.52
  text "0.39mil" at 59.797,146.448 h1.52
  text "3.5" at 76.303,146.448 h1.52
  text "1" at 3.932,143.4 h1.52
  text "Top Layer" at 14.343,143.4 h1.52
  text "1.38mil" at 59.797,143.4 h1.52
  text "Dielectric 1" at 14.343,140.352 h1.52
  text "FR-4" at 37.959,140.352 h1.52
  text "27.95mil" at 59.797,140.352 h1.52
  text "5" at 76.303,140.352 h1.52
  text "2" at 3.932,137.304 h1.52
  text "Bottom Layer" at 14.343,137.304 h1.52
  text "1.38mil" at 59.797,137.304 h1.52
  text "Bottom Solder" at 14.343,134.256 h1.52
  text "Solder Resist" at 37.959,134.256 h1.52
  text "0.39mil" at 59.797,134.256 h1.52
  text "3.5" at 76.303,134.256 h1.52
  text "Bottom Overlay" at 14.343,131.208 h1.52
Bottom Layer:
  region net VDDRF: 23.976,29.892 26.574,29.892 26.574,29.566 cw(c26.396,29.566) 26.396,29.388 24.561,29.388 24.561,22.576 ccw(c25.019,22.576) 25.019,22.118 25.2,22.118 23.976,21.847
  region net VDD: 31.362,4.197 31.642,4.478 cw(c32.466,3.655) 32.466,4.819 33.605,4.819 33.605,7.803 31.351,9.162 31.354,9.787 32.341,9.787 32.979,8.837 ccw(c33.339,9.079) 33.339,8.644 33.39,8.644 ccw(c33.39,9.07) 33.815,9.07 33.815,10.779 34.449,10.779 34.449,4.462 cw(c34.104,4.462) 34.103,4.117 31.393,4.121 cw(c31.393,4.165)
  region net VDD: 33.909,11.094 34.516,11.094 cw(c34.517,10.9) 34.654,11.037 34.794,10.897 cw(c34.624,10.728) 34.864,10.727 34.864,10.251 cw(c34.515,10.251) 34.515,9.902 33.926,9.902 cw(c33.926,10.147) 33.681,10.147 33.681,10.867 cw(c33.909,10.867)
  region net VDD: 26.89,17.386 26.89,17.997 cw(c27.071,17.997) 26.943,18.125 27.349,18.531 27.549,18.531 27.558,18.541 27.558,18.889 27.541,18.906 27.442,18.906 27.144,19.204 ccw(c26.959,19.019) 26.959,19.281 26.25,19.281 ccw(c26.25,19.109) 26.079,19.109 26.079,17.579 ccw(c26.289,17.579) 26.291,17.368 26.876,17.373 ccw(c26.876,17.386)
  region net VDDRF: 55.355,29.776 55.442,28.322 55.237,28.117 54.179,28.117 53.981,28.314 53.981,29.975 54.363,30.356 54.341,32.49 55.3,32.49 cw(c55.412,31.134)
  region net VDD: 55.355,4.264 55.442,5.718 55.237,5.923 54.179,5.923 53.981,5.726 53.981,4.065 54.363,3.684 54.341,1.55 55.3,1.55 ccw(c55.412,2.906)
  region net VDDRF: 29.997,21.733 30,22.274 cw(c30.53,22.27) 30.155,22.644 30.36,22.849 cw(c30.628,22.581) 30.628,22.96 30.892,22.96 cw(c30.892,22.582) 31.159,22.849 31.258,22.75 cw(c30.635,22.126) 31.517,22.126 31.517,21.733
  region net VDDRF: 31.673,20.299 31.919,20.299 cw(c31.919,20.127) 32.066,20.216 32.176,20.032 ccw(c32.335,20.128) 32.335,19.942 32.828,19.942 cw(c32.828,19.671) 33.019,19.863 33.175,19.707 cw(c32.914,19.446) 33.283,19.445 33.283,18.889 32.493,18.885 31.586,19.91 cw(c31.719,19.978) 31.57,19.978 31.57,20.196 cw(c31.673,20.196)
  region net VDDRF1V55: 28.527,19.683 28.527,20.233 29.322,21.029 cw(c29.84,20.511) 29.84,21.243 31.098,21.243 31.098,20.337 ccw(c31.187,20.337) 31.187,20.249 cw(c31.187,20.093) 31.343,20.093 31.343,18.941 cw(c31.261,18.941) 31.261,18.859 30.912,18.859 cw(c30.912,19.157) 30.614,19.157 30.614,19.605 ccw(c30.537,19.605) 30.537,19.683
  region net VDD: 21.501,11.716 20.936,11.716 cw(c20.936,11.97) 20.682,11.97 20.682,13.106 21.696,13.106 cw(c21.696,12.795) 22.006,12.795 22.006,12.398 cw(c21.58,12.398) 21.881,12.096
  region net VDDRF: 22.483,11.921 22.275,12.13 22.275,12.279 cw(c22.657,12.279) 22.387,12.55 22.532,12.695 cw(c22.661,12.566) 22.661,12.748 23.192,12.748 cw(c23.192,12.605) 23.335,12.605 23.335,12.128 cw(c23.163,12.128) 23.285,12.006 23.26,11.981 cw(c23.123,12.118) 23.124,11.924
  region net GND: 32.96,28.22 35.16,28.22 35.16,24.02 34.46,24.02 34.46,24.42 32.96,24.42
  pour cut-out: 24.64,12.54 25.44,12.54 25.44,11.14 24.64,11.14
  pour cut-out: 32.12,18.52 32.12,20.68 29.78,23.02 29.8,25.82 30.96,25.82 30.96,27.52 37.86,27.52 37.86,25.82 37.86,23.02 37.36,22.42 35.2,22.42 33.68,20.9 33.68,18.84 33.36,18.52
  pour cut-out: 21.56,15.24 23.28,15.24 23.28,14.52 23.32,14.48 23.3,14.46 23.3,13.56 21.64,13.56 21.56,13.64

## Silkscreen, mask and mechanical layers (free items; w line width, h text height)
Top Overlay:
  rectangle: 3.037,5.321 16.213,14.432
  lines w0.15: 6.902,30.775 6.902,31.275 ; 7.24,30.525 7.24,31.525 ; 7.577,30.371 7.577,31.678 ; 7.58,31.02 8.59,31.02 ; 44.771,33.083 46.078,33.083 ; 44.925,33.42 45.925,33.42 ; 45.175,33.758 45.675,33.758 ; 45.42,32.07 45.42,33.08 ; 49.849,33.089 51.156,33.089 ; 50.002,33.427 51.002,33.427 ; 50.252,33.764 50.752,33.764 ; 50.498,32.076 50.498,33.087 ; 52.385,33.072 53.691,33.072 ; 52.538,33.409 53.538,33.409 ; 52.788,33.747 53.288,33.747 ; 53.033,32.059 53.033,33.069 ; 57.48,33.1 58.787,33.1 ; 57.634,33.438 58.634,33.438 ; 57.884,33.776 58.384,33.776 ; 58.129,32.088 58.129,33.098 ; 59.24,3.833 60.115,4.339 ; 59.792,4.902 60.446,3.77 ; 60.161,4.938 60.661,4.072 ; 60.579,4.89 60.829,4.457
  text "VDDRF" at 54.106,32.564 h1
  text "PA15" at 16.403,32.547 h1
  text "PA14" at 19.092,32.546 h1
  text "PA13" at 21.773,32.546 h1
  text "PA12" at 24.458,32.546 h1
  text "PA11" at 27.135,32.546 h1
  text "PA10" at 29.696,32.547 h1
  text "PB12" at 32.378,32.546 h1
  text "PB2" at 35.056,32.546 h1
  text "PB0" at 37.236,32.547 h1
  text "PC13" at 39.421,32.537 h1
  text "VRPA" at 46.93,32.431 h1
  text "UART_TX" at 12.225,29.456 h1 r270
  text "UART_RX" at 14.68,29.456 h1 r270
  text "UART_TX" at 4.02,23.543 h1.5 r270
  text "UART_RX" at 7.193,23.543 h1.5 r270
  text "MB1791" at 9.237,18.873 h2.15
  text "Notes:" at 3.337,14.673 h1.2
  text "PB3" at 9.045,0.945 h1
  text "PB4" at 11.604,0.947 h1
  text "PB5" at 14.161,0.947 h1
  text "PB6" at 16.725,0.945 h1
  text "PB7" at 19.284,0.947 h1
  text "PB8" at 21.843,0.945 h1
  text "PA0" at 24.403,0.945 h1
  text "PA1" at 26.96,0.945 h1
  text "PA2" at 29.396,0.945 h1
  text "PA3" at 31.949,0.945 h1
  text "PA4" at 34.508,0.947 h1
  text "PA5" at 37.065,0.947 h1
  text "PA6" at 39.629,0.945 h1
  text "PA7" at 42.188,0.947 h1
  text "PA8" at 44.747,0.945 h1
  text "PA9" at 47.308,0.945 h1
  text "NRST" at 49.375,0.951 h1
  text "VDD" at 54.205,0.61 h1.5
Bottom Overlay:
  text "C" at 14.847,9.821 h10
  text "MB1791" at 16.097,7.171 h2.5
Top Paste:
  lines w0.5: 18,26.54 cw(c19.85,26.54) 19.85,28.39 ; 18.009,8.973 18.009,26.473 ; 18.02,9.04 ccw(c19.87,9.04) 19.87,7.19 ; 19.84,7.16 56.74,7.16 ; 19.84,28.4 56.74,28.4 ; 56.75,28.41 cw(c56.75,26.56) 58.6,26.56 ; 56.79,7.17 ccw(c56.79,9.02) 58.64,9.02 58.64,15.06 ; 58.6,17.517 58.6,26.51
Top Solder:
  rectangle: 36.72,18.5 37.46,19.22
  rectangle: 37.8,13.74 38.54,14.46
  lines w1.5: 58.584,17.638 58.584,26.326 ; 58.609,14.743 58.609,9.033 cw(c56.759,9.033) 56.759,7.183 19.859,7.183 cw(c19.859,9.033) 18.009,9.033 18.009,26.533 cw(c19.859,26.533) 19.859,28.383 56.759,28.383 cw(c56.759,26.533) 58.609,26.533
Mechanical 1:
  the board outline again, w0.3
Top Assembly:
  lines w0.1: 1.8,-0.122 70.384,-0.122 70.384,34.128 1.8,34.128 1.8,-0.122
Bottom Assembly:
  lines w0.1: 1.802,-0.121 1.802,34.129 70.385,34.129 70.385,-0.121 1.802,-0.121
Drill Drawing:
  lines w0.254: 3.862,118.142 5.555,118.142 4.709,116.449 3.862,118.142 ; 3.862,120.259 5.555,120.259 5.555,121.952 3.862,121.952 3.862,120.259
  lines w0.381: 2.343,115.306 327.322,115.306 ; 2.343,122.926 327.322,122.926 ; 16.335,111.496 16.335,126.736 ; 32.587,111.496 32.587,126.736 ; 60.265,111.496 60.265,126.736 ; 73.114,111.496 73.114,126.736 ; 91.753,111.496 91.753,126.736 ; 129.841,111.496 129.841,126.736 ; 144.824,111.496 144.824,126.736 ; 163.767,111.496 163.767,126.736 ; 180.273,111.496 180.273,126.736 ; 201.958,111.496 201.958,126.736 ; 235.832,111.496 235.832,126.736 ; 269.705,111.496 269.705,126.736 ; 291.696,111.496 291.696,126.736 ; 2.343,111.496 327.322,111.496 327.322,126.736 2.343,126.736 2.343,111.496
  text "Symbol" at 4.629,124.069 h1.83
  text "Count" at 17.478,124.069 h1.83
  text "Hole Size" at 33.73,124.069 h1.83
  text "Plated" at 61.408,124.069 h1.83
  text "Hole Type" at 74.257,124.069 h1.83
  text "Drill Layer Pair" at 92.896,124.069 h1.83
  text "Via/Pad" at 130.984,124.069 h1.83
  text "Pad Shape" at 145.967,124.069 h1.83
  text "Template" at 164.91,124.069 h1.83
  text "Description" at 181.416,124.069 h1.83
  text "Hole Tolerance (+)" at 203.101,124.069 h1.83
  text "Hole Tolerance (-)" at 236.975,124.069 h1.83
  text "Hole Length" at 270.848,124.069 h1.83
  text "Routed Path Length" at 292.839,124.069 h1.83
  text "44" at 17.478,120.259 h1.52
  text "1.000mm (39.37mil)" at 33.73,120.259 h1.52
  text "PTH" at 61.408,120.259 h1.52
  text "Round" at 74.257,120.259 h1.52
  text "Top Layer - Bottom Layer" at 92.896,120.259 h1.52
  text "Pad" at 130.984,120.259 h1.52
  text "(Mixed)" at 145.967,120.259 h1.52
  text "(Mixed)" at 164.91,120.259 h1.52
  text "-" at 270.848,120.259 h1.52
  text "-" at 292.839,120.259 h1.52
  text "1128" at 17.478,116.449 h1.52
  text "0.200mm (7.87mil)" at 33.73,116.449 h1.52
  text "PTH" at 61.408,116.449 h1.52
  text "Round" at 74.257,116.449 h1.52
  text "Top Layer - Bottom Layer" at 92.896,116.449 h1.52
  text "Via" at 130.984,116.449 h1.52
  text "Rounded" at 145.967,116.449 h1.52
  text "(Mixed)" at 164.91,116.449 h1.52
  text "-" at 270.848,116.449 h1.52
  text "-" at 292.839,116.449 h1.52
  text "1172 Total" at 17.478,112.639 h1.52
  text "mils" at 26.054,96.368 h2.54
  text "mils" at 37.107,96.368 h2.54

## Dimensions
70.459,-0.172 to 1.724,-0.151 on Bottom M14-Top Assembly/M15-Bottom Assembly
1.766,34.199 to 1.693,-0.188 on Bottom M14-Top Assembly/M15-Bottom Assembly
